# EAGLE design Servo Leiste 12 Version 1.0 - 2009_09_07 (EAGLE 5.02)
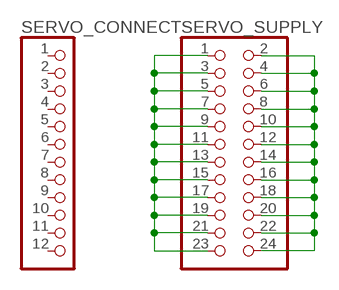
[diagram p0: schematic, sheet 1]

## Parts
SERVO_CONNECT  PINHD-1X12  [1X12]
SERVO_SUPPLY  PINHD-2X12  [2X12]

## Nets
N$1: SERVO_SUPPLY.1 SERVO_SUPPLY.3 SERVO_SUPPLY.5 SERVO_SUPPLY.7 SERVO_SUPPLY.9 SERVO_SUPPLY.11 SERVO_SUPPLY.13 SERVO_SUPPLY.15 SERVO_SUPPLY.17 SERVO_SUPPLY.19 SERVO_SUPPLY.21 SERVO_SUPPLY.23
N$2: SERVO_SUPPLY.2 SERVO_SUPPLY.4 SERVO_SUPPLY.6 SERVO_SUPPLY.8 SERVO_SUPPLY.10 SERVO_SUPPLY.12 SERVO_SUPPLY.14 SERVO_SUPPLY.16 SERVO_SUPPLY.18 SERVO_SUPPLY.20 SERVO_SUPPLY.22 SERVO_SUPPLY.24
Unconnected: SERVO_CONNECT.1 SERVO_CONNECT.2 SERVO_CONNECT.3 SERVO_CONNECT.4 SERVO_CONNECT.5 SERVO_CONNECT.6 SERVO_CONNECT.7 SERVO_CONNECT.8 SERVO_CONNECT.9 SERVO_CONNECT.10 SERVO_CONNECT.11 SERVO_CONNECT.12

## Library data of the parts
SERVO_CONNECT = pinheadRound:PINHD-1X12: PIN HEADER
SERVO_SUPPLY = pinheadRound:PINHD-2X12: PIN HEADER

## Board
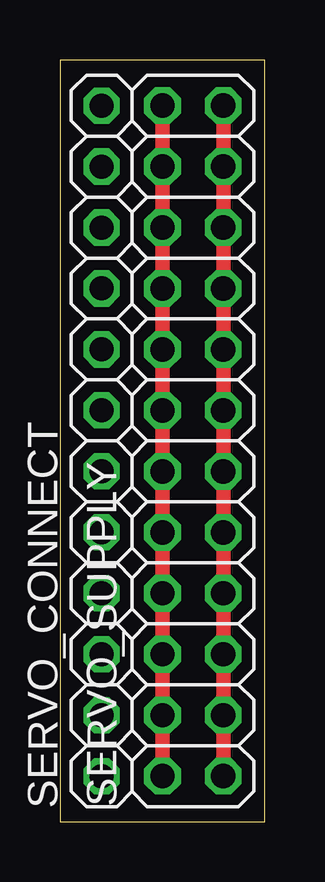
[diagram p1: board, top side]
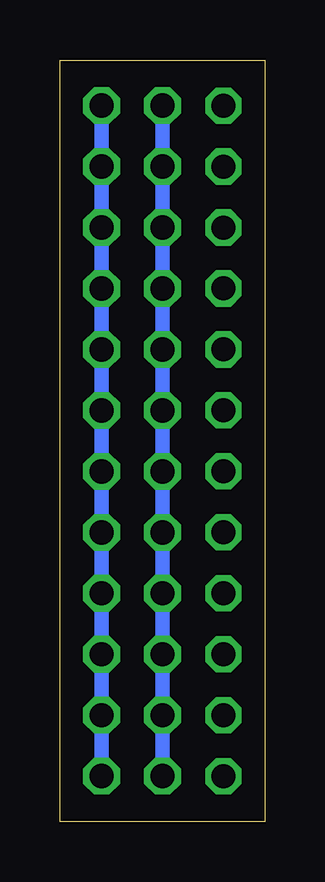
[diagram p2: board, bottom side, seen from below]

Size 8.56 x 31.74 mm. Coordinates in mm from the lower left corner, seen from the top.
Outline: 0,0 8.56,0 8.56,31.74 0,31.74 0,0
Copper layers (1*16): Top 0.035mm / dielectric 1.5mm / Bottom 0.035mm
Design rules "default": minimum track width 10mil, minimum drill 24mil, track to track 8mil, track to pad 8mil, pad to pad 8mil, via to via 8mil, smd to smd 8mil, copper to edge 40mil, drill to drill 8mil, minimum pad ring 10mil, minimum via ring 8mil, stop-mask expansion 4mil, vias tented up to drill 0mil, thermal gap 10mil

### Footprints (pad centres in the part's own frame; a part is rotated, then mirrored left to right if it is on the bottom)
1X12 = drill 1 octagon: 1 -13.97,0; 2 -11.43,0; 3 -8.89,0; 4 -6.35,0; 5 -3.81,0; 6 -1.27,0; 7 1.27,0; 8 3.81,0; 9 6.35,0; 10 8.89,0; 11 11.43,0; 12 13.97,0
2X12 = drill 1.016 octagon: 1 -13.97,-1.27; 2 -13.97,1.27; 3 -11.43,-1.27; 4 -11.43,1.27; 5 -8.89,-1.27; 6 -8.89,1.27; 7 -6.35,-1.27; 8 -6.35,1.27; 9 -3.81,-1.27; 10 -3.81,1.27; 11 -1.27,-1.27; 12 -1.27,1.27; 13 1.27,-1.27; 14 1.27,1.27; 15 3.81,-1.27; 16 3.81,1.27; 17 6.35,-1.27; 18 6.35,1.27; 19 8.89,-1.27; 20 8.89,1.27; 21 11.43,-1.27; 22 11.43,1.27; 23 13.97,-1.27; 24 13.97,1.27

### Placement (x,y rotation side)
SERVO_CONNECT  1.74,15.87 90 top
SERVO_SUPPLY  5.55,15.87 90 top

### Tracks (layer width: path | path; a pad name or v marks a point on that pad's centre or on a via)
N$1
  Top 0.61: SERVO_SUPPLY.23 SERVO_SUPPLY.1
  Bottom 0.61: SERVO_SUPPLY.23 SERVO_SUPPLY.21 SERVO_SUPPLY.19 SERVO_SUPPLY.17 SERVO_SUPPLY.15 SERVO_SUPPLY.13 SERVO_SUPPLY.11 SERVO_SUPPLY.9 SERVO_SUPPLY.7 SERVO_SUPPLY.5 SERVO_SUPPLY.3 SERVO_SUPPLY.1
N$2
  Top 0.61: SERVO_SUPPLY.24 SERVO_SUPPLY.2
  Bottom 0.61: SERVO_SUPPLY.24 SERVO_SUPPLY.22 SERVO_SUPPLY.20 SERVO_SUPPLY.18 SERVO_SUPPLY.16 SERVO_SUPPLY.14 SERVO_SUPPLY.12 SERVO_SUPPLY.10 SERVO_SUPPLY.8 SERVO_SUPPLY.6 SERVO_SUPPLY.4 SERVO_SUPPLY.2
